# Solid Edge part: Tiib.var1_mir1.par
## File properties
Author: jaanm
Template: Ansi Inch Part.par
Last saved by: jaanm
Revision: 2
Application: Solid Edge
Accuracy: 0,990
Username: jaanm
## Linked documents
Tiib.var1.par
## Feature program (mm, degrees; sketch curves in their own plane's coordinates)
part copy "CopiedPart_1"
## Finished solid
Body 1: solid body, 10 faces, 15 edges, 7 vertices.
  Faces by surface: spline 5, plane 3, cylinder 2
  Edges by curve: circle 5, spline 5, curve on surface 4, line 1
Bounding box of the edges (mm; curved faces can reach further): 1533.444 x 505.897 x 269.127, from (-20, -333.359, -49.7014) to (1513.4443, 172.5379, 219.4251).
Cylindrical faces by radius (mm): R5 x2
Planar faces by outward normal: -x 3
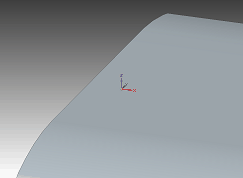
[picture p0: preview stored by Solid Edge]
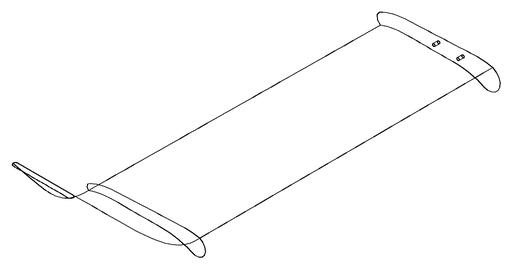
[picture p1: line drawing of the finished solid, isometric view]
